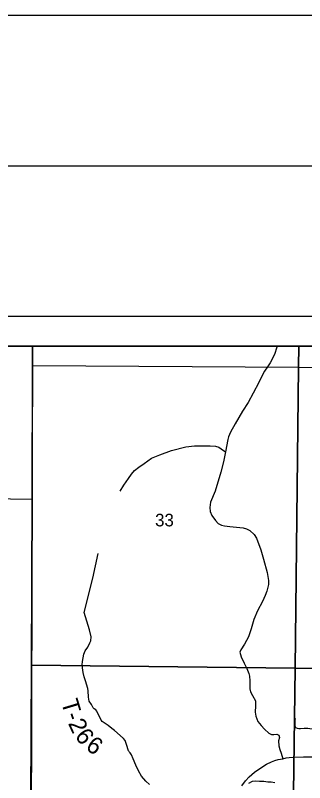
# Model space of a CAD drawing. Extents: x 0 to 34, y 0 to 22.
# Drawn here: x 6.424 to 7.387, y 19.45 to 22 of the extents above; entities that cross this region are included whole.
import ezdxf

# ---------------------------------------------------------------- set-up
doc = ezdxf.new("R2010")
doc.units = 0
for name, color, linetype in [('GM_X_Corporation', 7, 'Continuous'), ('GM_X_County_Road', 7, 'Continuous'), ('GM_X_Major_River', 7, 'Continuous'), ('GM_X_Section_Text', 7, 'Continuous'), ('GM_X_State_Route', 7, 'Continuous'), ('GM_X_Township_Road', 7, 'Continuous'), ('GM_X_Township_Road_Text', 7, 'Continuous'), ('GM_X_Township_Text', 7, 'Continuous'), ('SH_Border', 7, 'Continuous'), ('SH_Cut_Line', 7, 'Continuous'), ('SH_Data', 7, 'Continuous')]:
    doc.layers.add(name, color=color, linetype=linetype)

msp = doc.modelspace()

# ---------------------------------------------------------------- linework, layer by layer
at = {"layer": 'GM_X_Corporation'}
for points in [[(6.4812, 20.9), (5.4715, 20.9), (5.4711, 20.4076), (6.4797, 20.3917), (6.481, 20.8366)], [(7.3671, 20.9), (6.4812, 20.9), (6.481, 20.8366), (7.3663, 20.8308)], [(8.371, 20.9), (7.3671, 20.9), (7.3663, 20.8308), (8.3706, 20.8258)], [(7.3663, 20.8308), (7.3548, 19.8302), (6.4778, 19.8399), (6.4797, 20.3917), (6.481, 20.8366)], [(8.3706, 20.8258), (8.3645, 19.8193), (7.3548, 19.8302), (7.3663, 20.8308)], [(6.4797, 20.3917), (6.4778, 19.8399), (6.4758, 19.3912), (5.4696, 19.395), (5.4711, 20.4076)], [(7.3548, 19.8302), (7.3418, 18.8315), (6.4726, 18.8257), (6.4758, 19.3912), (6.4778, 19.8399)], [(8.3645, 19.8193), (8.353, 18.8213), (7.3418, 18.8315), (7.3548, 19.8302)]]:
    msp.add_lwpolyline(points, close=True, dxfattribs=at)
at = {"layer": 'GM_X_County_Road'}
msp.add_lwpolyline([(7.2948, 20.9), (7.2928, 20.8938), (7.2869, 20.8766), (7.2797, 20.86), (7.2718, 20.8452), (7.2631, 20.8323), (7.2524, 20.8169), (7.243, 20.7988), (7.2343, 20.7802), (7.2157, 20.744), (7.1984, 20.713), (7.1803, 20.6842), (7.155, 20.6418), (7.1396, 20.6146), (7.1329, 20.5987), (7.1312, 20.5905), (7.1235, 20.5491), (7.1163, 20.5164), (7.1079, 20.4814), (7.0883, 20.4189), (7.0737, 20.3818), (7.0707, 20.3646), (7.0721, 20.3512), (7.0774, 20.3373), (7.0895, 20.3205), (7.0987, 20.3113), (7.1103, 20.3056), (7.1203, 20.3031), (7.1376, 20.3009), (7.1817, 20.2969), (7.1934, 20.2934), (7.2043, 20.2877), (7.2189, 20.2748), (7.2261, 20.262), (7.2408, 20.2238), (7.2497, 20.1925), (7.2613, 20.1479), (7.2658, 20.1221), (7.2658, 20.1087), (7.2603, 20.0857), (7.2554, 20.0718), (7.2465, 20.0519), (7.2294, 20.0207), (7.2172, 19.9917), (7.2085, 19.9607), (7.1993, 19.9339), (7.186, 19.9101), (7.1738, 19.8913), (7.1708, 19.8831), (7.1753, 19.8675), (7.1852, 19.8474), (7.1939, 19.829), (7.2006, 19.8127), (7.2031, 19.8032), (7.2038, 19.7881), (7.2043, 19.7616), (7.2068, 19.7514), (7.2132, 19.7393), (7.2234, 19.7217), (7.2229, 19.7053), (7.2224, 19.684), (7.2244, 19.6711), (7.2308, 19.6532), (7.2415, 19.6396), (7.2532, 19.6277), (7.2673, 19.614), (7.276, 19.6096), (7.2839, 19.6096), (7.2938, 19.6108), (7.301, 19.6081), (7.3032, 19.5999), (7.2998, 19.5887), (7.3002, 19.5719), (7.304, 19.5604), (7.3084, 19.5479), (7.3135, 19.5294)], dxfattribs=at)
at = {"layer": 'GM_X_Major_River'}
msp.add_lwpolyline([(7.2873, 19.4492), (7.2748, 19.4509), (7.2642, 19.4512), (7.2505, 19.4533), (7.2365, 19.4539), (7.2244, 19.4542), (7.2123, 19.4537), (7.1999, 19.4467)], dxfattribs=at)
at = {"layer": 'GM_X_State_Route'}
msp.add_lwpolyline([(7.1773, 19.4395), (7.1895, 19.4558), (7.2023, 19.469), (7.2196, 19.4843), (7.2406, 19.4993), (7.26, 19.5111), (7.2763, 19.5188), (7.2873, 19.523), (7.2979, 19.5263), (7.3135, 19.5294), (7.3249, 19.532), (7.3355, 19.5334), (7.3518, 19.5347), (7.3822, 19.5358), (7.4105, 19.5358)], dxfattribs=at)
at = {"layer": 'GM_X_Township_Road'}
msp.add_line((7.1085, 20.5597), (7.1235, 20.5491), dxfattribs=at)
for points in [[(6.773, 20.4183), (6.7854, 20.4381), (6.8003, 20.4605), (6.811, 20.4745), (6.8209, 20.4877), (6.835, 20.4985), (6.8532, 20.5109), (6.8771, 20.5282), (6.9052, 20.5398), (6.9433, 20.5539), (6.9912, 20.5654), (7.0201, 20.5696), (7.0722, 20.5687), (7.0904, 20.5679), (7.1014, 20.5647), (7.1085, 20.5597)], [(6.8012, 19.5545), (6.8007, 19.5552), (6.7935, 19.5768), (6.7891, 19.59), (6.7845, 19.5964), (6.773, 19.6069), (6.7544, 19.6228), (6.7456, 19.6299), (6.7326, 19.6396), (6.7132, 19.6528), (6.7099, 19.6576), (6.6948, 19.6877), (6.6914, 19.6913), (6.686, 19.6951), (6.6828, 19.6982), (6.6776, 19.7093), (6.6701, 19.7209), (6.6678, 19.7344), (6.6667, 19.7551), (6.6655, 19.7632), (6.6576, 19.7877), (6.6527, 19.8011), (6.6499, 19.8155), (6.6478, 19.8312), (6.6464, 19.8415), (6.6477, 19.8526), (6.6525, 19.8765), (6.6569, 19.8873), (6.6653, 19.9005), (6.6719, 19.9141), (6.6751, 19.9211), (6.6762, 19.9342), (6.6706, 19.9576), (6.6528, 20.0149), (6.682, 20.1293), (6.6992, 20.2111)], [(7.4354, 19.6262), (7.4181, 19.6264), (7.397, 19.6293), (7.3853, 19.6296), (7.3731, 19.629), (7.3671, 19.6286), (7.3629, 19.6292), (7.3576, 19.6319), (7.3561, 19.6347), (7.3549, 19.6397), (7.3547, 19.6516), (7.355, 19.6572), (7.3556, 19.663)], [(6.8704, 19.4431), (6.8577, 19.4552), (6.8439, 19.4708), (6.8344, 19.4891), (6.8249, 19.5078), (6.8156, 19.5294), (6.811, 19.5419), (6.8066, 19.549), (6.8028, 19.5522), (6.8012, 19.5545)]]:
    msp.add_lwpolyline(points, dxfattribs=at)
at = {"layer": 'GM_X_Township_Text'}
for points in [[(6.4525, 17.3965), (6.4653, 18.1777), (6.4655, 18.1862), (6.4767, 18.8745), (6.4767, 18.8755), (6.4827, 20.9), (2.1, 20.9), (2.1, 19.4241)], [(8.9, 16.8499), (8.9, 20.9), (6.4827, 20.9)]]:
    msp.add_lwpolyline(points, dxfattribs=at)
at = {"layer": 'SH_Border'}
msp.add_lwpolyline([(1.5, 21.5), (33.5, 21.5), (33.5, 0.5), (1.5, 0.5)], close=True, dxfattribs=at)
at = {"layer": 'SH_Cut_Line'}
msp.add_lwpolyline([(0, 0), (34, 0), (34, 22), (0, 22)], close=True, dxfattribs=at)
at = {"layer": 'SH_Data'}
for p, q in [((2, 21), (9, 21)), ((2.1, 20.9), (8.9, 20.9))]:
    msp.add_line(p, q, dxfattribs=at)

# ---------------------------------------------------------------- texts
at = {"layer": 'GM_X_Section_Text'}
msp.add_text('33', height=0.04186, rotation=0, dxfattribs=at).set_placement((6.8891, 20.3015))
at = {"layer": 'GM_X_Township_Road_Text'}
for s, rotation, p in [('T', 286.7366, (6.5758, 19.718)), ('2', 294.7249, (6.5987, 19.6471)), ('-', 289.0523, (6.5888, 19.6749)), ('6', 306.8832, (6.6201, 19.6041)), ('6', 324.8057, (6.6549, 19.5626))]:
    msp.add_text(s, height=0.0568, rotation=rotation, dxfattribs=at).set_placement(p)

doc.saveas('drawing.dxf')
